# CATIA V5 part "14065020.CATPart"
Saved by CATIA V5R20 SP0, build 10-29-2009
Part number: 14065020
Definition: NONE
Nomenclature: 14065020
Source: Unknown
Description: 14065020
Bounding box of the stored display mesh (mm): x -10 to 40, y -46.5 to 36.6, z -36.6 to 36.6
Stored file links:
  C:\Users\Utente\Desktop\IO LAVORO\3D X SITO CF\X SITO\PLASTICA\RF2\14065020.CATPart
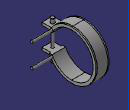
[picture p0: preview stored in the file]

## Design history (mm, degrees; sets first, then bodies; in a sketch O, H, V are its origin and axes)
Body1 "14065020" (main body)
  Solid1: solid without history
